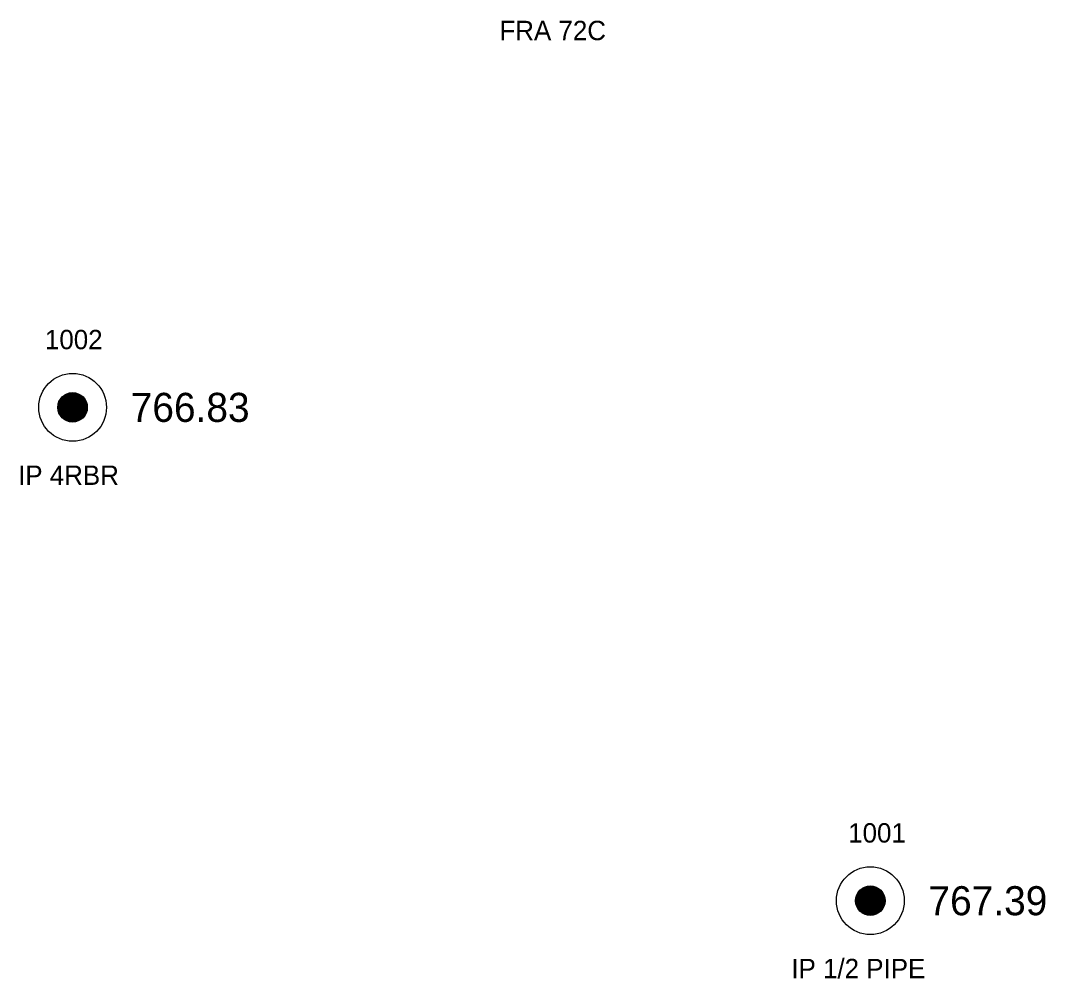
# Model space of a CAD drawing. Extents: x 1736563 to 1738032, y 1150548 to 1154248.
# Drawn here: x 1736872.9 to 1736925.8, y 1151010.5 to 1151060 of the extents above; entities that cross this region are included whole.
import ezdxf

# ---------------------------------------------------------------- set-up
doc = ezdxf.new("R2010")
doc.units = 0
for name, color, linetype in [('RD_EX_DV_Prop_txCode', 7, 'Continuous'), ('RD_EX_DV_PropPin', 7, 'Continuous'), ('RD_EX_Fence_Other_txCode', 7, 'Continuous'), ('RD_EX_TX_DV_Prop_ELEV', 7, 'Continuous'), ('RD_SMD_Locator', 7, 'Continuous')]:
    doc.layers.add(name, color=color, linetype=linetype)

msp = doc.modelspace()

# ---------------------------------------------------------------- linework, layer by layer
at = {"layer": 'RD_EX_DV_PropPin'}
for p, q in [((1736875.493, 1151039.259), (1736875.493, 1151040.755)), ((1736875.528, 1151039.253), (1736875.528, 1151040.761)), ((1736875.563, 1151039.249), (1736875.563, 1151040.765)), ((1736875.598, 1151039.247), (1736875.598, 1151040.767)), ((1736875.633, 1151039.246), (1736875.633, 1151040.768)), ((1736875.668, 1151039.247), (1736875.668, 1151040.767)), ((1736875.703, 1151039.249), (1736875.703, 1151040.765)), ((1736875.738, 1151039.253), (1736875.738, 1151040.761)), ((1736875.773, 1151039.259), (1736875.773, 1151040.755)), ((1736874.932, 1151039.709), (1736874.932, 1151040.305)), ((1736874.967, 1151039.637), (1736874.967, 1151040.377)), ((1736875.002, 1151039.58), (1736875.002, 1151040.434)), ((1736875.037, 1151039.533), (1736875.037, 1151040.481)), ((1736875.072, 1151039.492), (1736875.072, 1151040.522)), ((1736875.107, 1151039.456), (1736875.107, 1151040.558)), ((1736875.142, 1151039.425), (1736875.142, 1151040.589)), ((1736875.177, 1151039.397), (1736875.177, 1151040.617)), ((1736875.212, 1151039.372), (1736875.212, 1151040.642)), ((1736875.247, 1151039.351), (1736875.247, 1151040.663)), ((1736875.282, 1151039.331), (1736875.282, 1151040.683)), ((1736875.317, 1151039.314), (1736875.317, 1151040.7)), ((1736875.352, 1151039.299), (1736875.352, 1151040.715)), ((1736875.387, 1151039.287), (1736875.387, 1151040.727)), ((1736875.422, 1151039.276), (1736875.422, 1151040.738)), ((1736875.458, 1151039.266), (1736875.458, 1151040.748)), ((1736875.808, 1151039.266), (1736875.808, 1151040.748)), ((1736875.843, 1151039.276), (1736875.843, 1151040.738)), ((1736875.878, 1151039.287), (1736875.878, 1151040.727)), ((1736875.913, 1151039.299), (1736875.913, 1151040.715)), ((1736875.948, 1151039.314), (1736875.948, 1151040.7)), ((1736875.983, 1151039.331), (1736875.983, 1151040.683)), ((1736876.018, 1151039.351), (1736876.018, 1151040.663)), ((1736876.053, 1151039.372), (1736876.053, 1151040.642)), ((1736876.088, 1151039.397), (1736876.088, 1151040.617)), ((1736876.123, 1151039.425), (1736876.123, 1151040.589)), ((1736876.158, 1151039.456), (1736876.158, 1151040.558)), ((1736876.193, 1151039.492), (1736876.193, 1151040.522)), ((1736876.228, 1151039.533), (1736876.228, 1151040.481)), ((1736876.263, 1151039.58), (1736876.263, 1151040.434)), ((1736876.298, 1151039.637), (1736876.298, 1151040.377)), ((1736876.333, 1151039.709), (1736876.333, 1151040.305)), ((1736874.897, 1151039.811), (1736874.897, 1151040.203)), ((1736876.368, 1151039.811), (1736876.368, 1151040.203)), ((1736916.102, 1151014.251), (1736916.102, 1151014.847)), ((1736916.137, 1151014.18), (1736916.137, 1151014.919)), ((1736916.172, 1151014.123), (1736916.172, 1151014.976)), ((1736916.207, 1151014.075), (1736916.207, 1151015.023)), ((1736916.242, 1151014.034), (1736916.242, 1151015.064)), ((1736916.277, 1151013.999), (1736916.277, 1151015.1)), ((1736916.312, 1151013.967), (1736916.312, 1151015.131)), ((1736916.347, 1151013.939), (1736916.347, 1151015.159)), ((1736916.382, 1151013.915), (1736916.382, 1151015.184)), ((1736916.417, 1151013.893), (1736916.417, 1151015.206)), ((1736916.452, 1151013.874), (1736916.452, 1151015.225)), ((1736916.487, 1151013.857), (1736916.487, 1151015.242)), ((1736916.522, 1151013.842), (1736916.522, 1151015.257)), ((1736916.557, 1151013.829), (1736916.557, 1151015.27)), ((1736916.592, 1151013.818), (1736916.592, 1151015.281)), ((1736916.627, 1151013.809), (1736916.627, 1151015.29)), ((1736916.662, 1151013.801), (1736916.662, 1151015.297)), ((1736916.697, 1151013.796), (1736916.697, 1151015.303)), ((1736916.732, 1151013.792), (1736916.732, 1151015.307)), ((1736916.767, 1151013.789), (1736916.767, 1151015.31)), ((1736916.802, 1151013.788), (1736916.802, 1151015.31)), ((1736916.837, 1151013.789), (1736916.837, 1151015.31)), ((1736916.872, 1151013.792), (1736916.872, 1151015.307)), ((1736916.907, 1151013.796), (1736916.907, 1151015.303)), ((1736916.942, 1151013.801), (1736916.942, 1151015.297)), ((1736916.977, 1151013.809), (1736916.977, 1151015.29)), ((1736917.012, 1151013.818), (1736917.012, 1151015.281)), ((1736917.047, 1151013.829), (1736917.047, 1151015.27)), ((1736917.082, 1151013.842), (1736917.082, 1151015.257)), ((1736917.117, 1151013.857), (1736917.117, 1151015.242)), ((1736917.152, 1151013.874), (1736917.152, 1151015.225)), ((1736917.187, 1151013.893), (1736917.187, 1151015.206)), ((1736917.222, 1151013.915), (1736917.222, 1151015.184)), ((1736917.257, 1151013.939), (1736917.257, 1151015.159)), ((1736917.292, 1151013.967), (1736917.292, 1151015.131)), ((1736917.327, 1151013.999), (1736917.327, 1151015.1)), ((1736917.362, 1151014.034), (1736917.362, 1151015.064)), ((1736917.397, 1151014.075), (1736917.397, 1151015.023)), ((1736917.432, 1151014.123), (1736917.432, 1151014.976)), ((1736917.467, 1151014.18), (1736917.467, 1151014.919)), ((1736917.502, 1151014.251), (1736917.502, 1151014.847)), ((1736916.067, 1151014.353), (1736916.067, 1151014.745)), ((1736917.537, 1151014.353), (1736917.537, 1151014.745))]:
    msp.add_line(p, q, dxfattribs=at)
for centre, radius in [((1736875.633, 1151040.007), 1.75), ((1736875.633, 1151040.007), 0.761), ((1736916.802, 1151014.549), 1.75), ((1736916.802, 1151014.549), 0.761)]:
    msp.add_circle(centre, radius, dxfattribs=at)
at = {"layer": 'RD_SMD_Locator'}
for centre in [(1736875.633, 1151040.007), (1736916.802, 1151014.549)]:
    msp.add_circle(centre, 0.15, dxfattribs=at)

# ---------------------------------------------------------------- texts
at = {"layer": 'RD_EX_DV_Prop_txCode'}
for s, p in [('1002', (1736874.207, 1151043.007)), ('IP 4RBR', (1736872.822, 1151036.007)), ('1001', (1736915.66, 1151017.549)), ('IP 1/2 PIPE', (1736912.727, 1151010.549))]:
    msp.add_text(s, height=1, dxfattribs=at).set_placement(p)
at = {"layer": 'RD_EX_Fence_Other_txCode'}
msp.add_text('FRA 72C', height=1, dxfattribs=at).set_placement((1736897.662, 1151058.956))
at = {"layer": 'RD_EX_TX_DV_Prop_ELEV'}
for s, p in [('766.83', (1736878.633, 1151039.257)), ('767.39', (1736919.802, 1151013.799))]:
    msp.add_text(s, height=1.5, dxfattribs=at).set_placement(p)

doc.saveas('drawing.dxf')
